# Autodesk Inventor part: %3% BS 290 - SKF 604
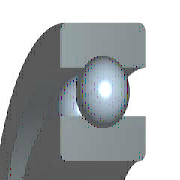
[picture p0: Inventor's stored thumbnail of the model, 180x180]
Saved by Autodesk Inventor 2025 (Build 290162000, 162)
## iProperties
Created: 2024-01
Part Number: %3% BS 290 - SKF 604
Material: Acciaio, Dolce
Description: Cuscinetti a sfere a fila singola
Document SubType Name: Modeling
Standard: BS 290
Designer: Ryzen5700u
Standards Organization: BSI
Language: it-IT
Size Designation: SKF 604
Categories: <MemberInstance><Categories><Category DisplayName="Parti albero" InternalName="7f7aeb1f-a693-4053-b835-cee3144e0d98" Mnemonic="SHFT"><Category DisplayName="Cusc
Density: 7.85 g/cm^3
Appearance: Semilucidato
IsCustomPart: 0
Author: Ryzen5700u
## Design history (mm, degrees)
node "WorkPoint1"
node "WorkAxis1"
node "WorkPlane3"
node "WorkPlane4"
node "WorkPoint2"
pattern_circular "Seriepolare1" dims "d17" = 54 (= msp_pocet), angle "d19" = 360 deg
body "Solid1"
node "Schizzo1"
revolve "Rivoluzione1" stored, may be unused: angle "d6" = 360 deg
revolve "Rivoluzione2" stored, may be unused: angle "d10" = 360 deg
node "Schizzo4"
revolve "Rivoluzione3" stored, may be unused: angle "d16" = 360 deg
fillet "Raccordo1" dims "d20" = 0.2 (= r)
sketch "Schizzo2"
  geometry: L1 (2, 4)-(6, 4); L2 (2, 0)-(2, 4); L3 (6, 0)-(2, 0); L4 (6, 4)-(6, 0); L5 (0, 0)-(0, 20); L6 (0, 0)-(0, 20); L7 (-7.2, 0)-(43.2, 0) reference
  constraints: 12 end point, 3 vertical, 2 horizontal, 1 collinear, 1 other
  dimensions: "d1" = 4 vertical distance of L1.start L5 (= Diam); "d3" = 12 diameter of L1.end L5 (= DD); "d5" = 4 distance of L2.start L1.start (= msp_mdtd2)
sketch "Schizzo3"
  geometry: L1 (4.72, 4)-(4.72, 2.96); L2 (3.28, 4)-(4.72, 4); L3 (3.28, 2.96)-(3.28, 4); L4 (3.28, 0)-(3.28, 1.04); L5 (4.72, 0)-(3.28, 0); L6 (4.72, 1.04)-(4.72, 0); L7 (6, 0)-(-6, 0) reference; L8 (6, 4)-(-6, 4) reference; L9 (0, -42.29)-(0, 61.29); L10 (0, 82.007)-(0, -63.007) reference; A1 r 1.2 centre (4, 2) between (4.72, 1.04) and (4.72, 2.96); A2 r 1.2 centre (4, 2) between (3.28, 2.96) and (3.28, 1.04)
  constraints: 14 end point, 4 collinear, 4 point on circle, 4 vertical, 2 centre point, 2 concentric, 2 horizontal, 2 point on line
  dimensions: "d9" = 2.4 diameter of A1 (= msp_mdtd6); "d21" = 3.28 distance between parallel lines of L9 L4 (= 0.5 x msp_d1); "d22" = 4 distance from line of L9 A1.centre (= 0.5 x msp_ds); "d23" = 4.72 distance between parallel lines of L9 L6 (= 0.5 x msp_dd1)
sketch "Schizzo5"
  geometry: L1 (4, 0.8)-(4, 3.2); L2 (4.72, 0)-(-4.72, 0) reference; L3 (4, 0.8)-(4, 3.2); A1 r 1.2 centre (4, 2) between (4, 0.8) and (4, 3.2); A2 r 1.2 centre (4, 2) between (4.72, 1.04) and (4.72, 2.96) reference
  constraints: 4 end point, 2 point on circle, 1 centre point, 1 concentric, 1 vertical
  dimensions: "d13" = 0 horizontal distance of A1.centre L1.start; "d15" = 2.4001 diameter of A1 (computed from msp_mdtd6)
other parameters: "Diam" = 4 [user parameter; used in 3 equation terms], "DD" = 12 [user parameter; used in 3 equation terms], "B" = 4 [user parameter; used in 1 equation term], "r" = 0.2 [user parameter; used in 1 equation term], "msp_ds" = 8 (= 0.5 x Diam + 0.5 x DD) [user parameter; used in 5 equation terms], "msp_d0" = 2.4 (= -0.3 x Diam + 0.3 x DD) [user parameter; used in 4 equation terms], "msp_d1" = 6.56 (= msp_ds - 0.6 x msp_d0) [user parameter; used in 1 equation term], "msp_dd1" = 9.44 (= msp_ds + 0.6 x msp_d0) [user parameter; used in 1 equation term], "msp_pom" = 12 (= 1.5 x msp_ds) [user parameter; used in 1 equation term], "msp_mdtd2" = 4 (= B) [user parameter; used in 3 equation terms], "msp_mdtd4" = 8 (= msp_ds) [user parameter], "msp_mdtd6" = 2.4 (= msp_d0) [user parameter; used in 2 equation terms], "msp_mdtd7" = 2 (= 0.5 x msp_mdtd2) [user parameter], "msp_pocet" = 54 (computed from msp_d0, msp_pom) [user parameter; used in 1 equation term], "d2" = 72 (derived), "d4" = 19 (derived), "d7" = 0, "d8" = 15.6 (derived), "d11" = -4 (computed from msp_mdtd2), "d12" = 0 (derived), "d14" = 15.6001 (derived), "d26" = 0, "d27" = 0, "d28" = 0, "d29" = 0, "d30" = 0
